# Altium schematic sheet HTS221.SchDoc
size A
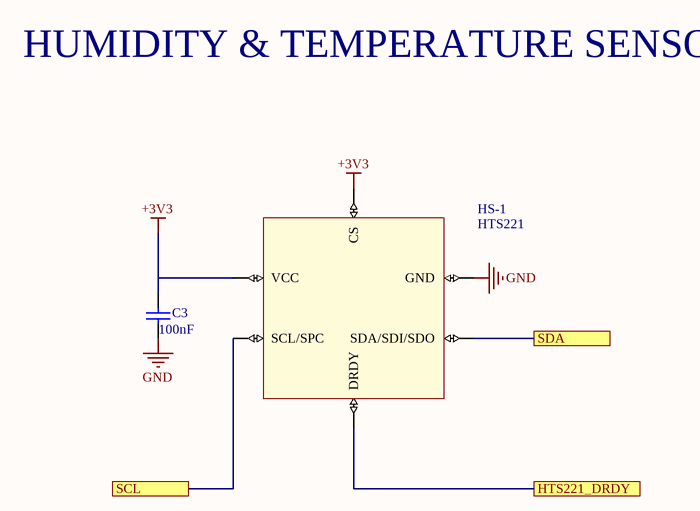
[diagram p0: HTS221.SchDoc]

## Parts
C3  value 100nF  [CAP-0402]  (hidden comment: C0402C104K3PACTU)
HS-1  HTS221  [HTS221]

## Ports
HTS221_DRDY, SCL, SDA

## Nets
+3V3: C3.2 HS-1.1(VCC) HS-1.6(CS)
GND: C3.1 HS-1.5(GND)
HTS221_DRDY: HS-1.3(DRDY) ; port HTS221_DRDY
SCL: HS-1.2(SCL/SPC) ; port SCL
SDA: HS-1.4(SDA/SDI/SDO) ; port SDA

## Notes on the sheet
- HUMIDITY & TEMPERATURE SENSOR

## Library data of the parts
C3 = C0014-A.3: CAP CHIP 0402 100nF 25V X5R 10%; Manufacturer: KEMET; Code Arduino: 0132
HS-1 = U0006-A.3: SENS HUMIDITY 6% 3.6V; Manufacturer: STMicroelectronics; Min Supply Voltage: 1.7V; Code Arduino: A5356; Device Type: SENSOR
